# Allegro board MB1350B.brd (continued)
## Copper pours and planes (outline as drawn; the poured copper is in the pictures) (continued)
GND on TOP (solid shape): 73.03,140.5 72.52,141 72.01,140.49 72.01,141.86 73.03,141.86
GND on TOP: 72.14,125.35 69.98,127.51 69.98,138.18 73.41,138.18 73.41,139.06 72.39,139.06 72.39,140.84 69.98,140.84 69.98,148.72 72.39,151.13 92.08,151.13 95.25,147.96 95.25,126.49 94.11,125.35
GND on TOP: 58.55,54.86 61.98,54.86 62.36,54.48 65.91,54.48 66.17,54.23 66.17,52.45 65.79,52.07 62.74,52.07 61.59,53.21 58.8,53.21 58.55,52.96 58.55,51.69 58.29,51.44 55.37,51.44 55.12,51.69 55.12,53.72 55.37,53.98 57.66,53.98
GND on TOP: outline of 179 points within 0.51,0.51 113.79,172.21 ; 3 cut-outs
GND on TOP: 1.27,145.03 0.64,144.4 0.64,62.48 1.14,61.98 12.95,61.98 13.84,62.87 13.84,66.42 12.19,68.07 5.97,68.07 2.16,71.88 2.16,106.43 3.43,107.7 3.43,110.36 2.92,110.87 2.92,114.05 3.56,114.68 5.59,114.68 6.73,115.82 16.89,115.82 17.4,116.33 17.4,126.11 19.56,128.27 28.45,128.27 33.53,123.19 39.88,123.19 41.4,124.71 48.77,124.71 51.82,127.76 51.82,132.08 48.64,135.25 34.42,135.25 34.42,137.54 34.29,137.67 27.56,137.67 26.92,138.3 26.92,140.97 27.3,141.35 33.91,141.35 34.16,141.6 34.16,144.27 33.4,145.03 ; 1 cut-out
GND on TOP: 58.67,43.43 62.1,43.43 62.48,43.05 64.26,43.05 64.39,42.93 64.39,41.02 64.01,40.64 62.87,40.64 61.72,41.78 58.93,41.78 58.67,41.53 58.67,40.26 58.42,40.01 55.5,40.01 55.24,40.26 55.24,42.29 55.5,42.55 57.78,42.55
GND on TOP: 58.67,31.37 62.1,31.37 62.48,30.99 64.01,30.99 64.52,30.48 64.52,28.83 64.26,28.57 62.87,28.57 61.72,29.72 58.93,29.72 58.67,29.46 58.67,28.19 58.42,27.94 55.5,27.94 55.24,28.19 55.24,30.23 55.5,30.48 57.78,30.48
GND on TOP: 5.84,95.89 12.19,95.89 20.45,87.63 20.45,85.47 19.43,84.45 6.1,84.45 4.7,85.85 4.7,94.74
GND on BOTTOM: 26.04,82.17 42.67,82.17 44.32,80.52 44.32,66.29 49.28,61.34 49.28,57.53 47.75,56.01 29.46,56.01 26.92,58.55 26.92,65.66 25.53,67.06 25.53,81.66
GND on BOTTOM: outline of 126 points within 0.51,0.51 113.79,172.21 ; 2 cut-outs
GND on BOTTOM: 5.84,95.63 12.06,95.63 13.84,93.85 13.84,82.07 13.11,81.33 13.11,61.93 12.52,61.34 4.83,61.34 4.19,61.98 4.19,93.98
GND on BOTTOM: 62.74,80.77 80.26,80.77 80.77,80.26 89.92,80.26 90.17,80.01 90.17,72.9 86.11,68.83 86.11,62.61 84.84,61.34 66.93,61.34 54.61,73.66 48.9,73.66 47.88,74.68 47.88,79.38 49.28,80.77 53.21,80.77 53.21,79.25 53.85,78.61 56.26,78.61 57.4,79.76 61.72,79.76
GND on L3_GND: 0.51,0.51 0.51,172.21 113.79,172.21 113.79,109.65 113.51,108.97 113.26,107.19 112.93,104.8 113,102.74 113,101.3 113.44,98.76 113.79,97.38 113.79,0.51
VDD on L2_VCC: outline of 105 points within 27.43,0.51 113.79,154.43
VDD_ADJ on TOP: 66.42,55.37 66.04,54.99 62.48,54.99 62.23,55.24 61.21,55.24 60.96,55.5 60.96,63.12 59.82,64.26 53.85,64.26 53.47,64.64 53.47,66.67 54.1,67.31 65.79,67.31 66.42,66.67
VDD_ANA on TOP: 74.17,42.29 76.83,42.29 77.22,41.91 77.22,40.13 76.96,39.88 72.01,39.88 71.75,40.13 71.75,40.64 73.03,41.91 73.79,41.91
VDD_MCU on TOP (solid shape): 53.75,105.54 53.24,105.03 52.32,105.03 52.32,106.05 53.24,106.05
BOOTLOADER_RESET on TOP (solid shape): 45.73,54.76 45.22,54.25 44.3,54.25 44.3,55.27 45.22,55.27
E5V on TOP: 18.41,41.4 18.41,46.86 18.03,47.24 14.61,47.24 13.21,45.85 2.54,45.85 1.52,44.83 1.52,42.04 3.05,40.51 5.08,40.51 5.78,41.21 6.86,41.21 7.05,41.02 18.03,41.02
NETB2_2 on TOP (solid shape): 59.56,15.14 59.56,14.22 58.55,14.22 58.55,15.14 59.05,15.65
NETB3_1 on TOP (solid shape): 77.47,21.37 77.47,20.45 76.45,20.45 76.45,21.37 76.96,21.88
NETB3_2 on TOP (solid shape): 74.3,21.37 74.3,20.45 73.28,20.45 73.28,21.37 73.79,21.88
NETB3_3 on TOP (solid shape): 70.99,21.37 70.99,20.45 69.98,20.45 69.98,21.37 70.48,21.88
NETB3_4 on TOP (solid shape): 80.64,21.37 80.64,20.45 79.63,20.45 79.63,21.37 80.14,21.88
NETB3_6 on TOP (solid shape): 83.69,21.37 83.69,20.45 82.68,20.45 82.68,21.37 83.19,21.88
NETC11_2 on TOP (solid shape): 49.15,157.48 48.13,157.48 48.13,158.84 48.64,158.34 49.15,158.85
NETC26_2 on TOP: 42.93,119.51 48.26,119.51 48.64,119.13 48.64,117.22 48.01,116.59 44.83,116.59 44.45,116.2 44.45,112.9 44.07,112.52 42.8,112.52 42.55,112.78 42.55,119.13
NETC63_1 on TOP (solid shape): 51.71,50.95 50.79,50.95 50.29,51.46 50.79,51.97 51.71,51.97
NETC63_2 on TOP (solid shape): 48.54,50.95 47.62,50.95 47.11,51.46 47.62,51.97 48.54,51.97
NETC63_2 on TOP (solid shape): 50.03,51.46 50.54,50.95 49.17,50.95 49.17,51.97 50.54,51.97
NETC79_1 on TOP: 14.99,29.59 19.05,29.59 19.56,30.1 19.56,37.97 18.92,38.61 15.37,38.61 14.86,38.1 14.86,33.53 14.73,33.4 14.73,29.84
NETC79_2 on TOP: 9.91,19.68 3.17,19.68 2.16,20.7 2.16,31.5 9.27,38.61 13.46,38.61 14.22,37.85 14.22,30.23 14.1,30.1 8.26,30.1 7.87,29.72 7.87,24.77 10.41,22.23 10.41,20.19
NETC90_2 on TOP (solid shape): 91.44,15.02 91.44,14.1 90.42,14.1 90.42,15.02 90.93,15.53
NETCN8_10 on TOP (solid shape): 110.24,112.9 109.32,112.9 108.81,113.41 109.32,113.92 110.24,113.92
NETCN9_18 on TOP (solid shape): 53.47,80.39 52.45,80.39 52.45,81.75 52.96,81.25 53.47,81.76
NETCN9_19 on TOP (solid shape): 49.66,81.31 49.66,80.39 48.64,80.39 48.64,81.31 49.15,81.82
NETCN10_13 on TOP (solid shape): 62.1,82.01 61.59,81.5 61.09,82.01 61.09,82.93 62.1,82.93
NETCN10_15 on TOP (solid shape): 58.04,82.01 57.53,81.5 57.02,82.01 57.02,82.93 58.04,82.93
NETCN10_20 on BOTTOM (solid shape): 84.2,82.42 82.84,82.42 83.35,82.93 82.84,83.44 84.2,83.44
NETCN10_22 on BOTTOM (solid shape): 84.2,80.9 82.84,80.9 83.35,81.41 82.84,81.92 84.2,81.92
NETCN11_9 on TOP (solid shape): 48.54,47.14 47.62,47.14 47.11,47.65 47.62,48.16 48.54,48.16
NETCN11_9 on TOP (solid shape): 50.6,47.65 50.1,47.14 49.17,47.14 49.17,48.16 50.1,48.16
NETCN14_1 on TOP (solid shape): 94.23,59.44 93.31,59.44 92.81,59.94 93.31,60.45 94.23,60.45
NETCN16_1 on TOP: 14.35,29.21 16.26,29.21 16.76,28.7 16.76,25.65 14.99,23.88 9.91,23.88 8.64,25.15 8.64,29.21 9.02,29.59 13.97,29.59
NETR13_1 on TOP (solid shape): 53.69,141.35 54.2,140.84 52.83,140.84 52.83,141.86 54.19,141.86
NETR34_1 on TOP (solid shape): 97.41,107.95 96.49,107.95 95.98,108.46 96.49,108.97 97.41,108.97
NETR40_1 on TOP (solid shape): 38.51,84.71 38,84.2 37.08,84.2 37.08,85.22 38,85.22
NETR56_1 on TOP (solid shape): 88.8,65.28 88.3,64.77 87.38,64.77 87.38,65.79 88.3,65.79
NETR57_1 on TOP (solid shape): 91.69,66.39 91.19,65.88 90.68,66.39 90.68,67.31 91.69,67.31
NETR76_1 on TOP (solid shape): 97.41,106.43 96.49,106.43 95.98,106.93 96.49,107.44 97.41,107.44
NETR77_1 on TOP (solid shape): 46.85,51.46 47.36,50.95 46,50.95 46,51.97 47.36,51.97
NETR82_2 on TOP (solid shape): 51.71,47.14 50.35,47.14 50.86,47.65 50.35,48.16 51.71,48.16
NETR85_1 on TOP (solid shape): 46.85,47.65 47.36,47.14 46,47.14 46,48.16 47.36,48.16
NETR101_1 on TOP (solid shape): 25.27,24 24.26,24 24.26,25.36 24.76,24.86 25.27,25.37
NETR102_1 on TOP (solid shape): 26.92,24 25.91,24 25.91,25.36 26.41,24.86 26.92,25.37
NETR103_1 on TOP (solid shape): 28.57,24 27.56,24 27.56,25.36 28.06,24.86 28.57,25.37
NETR104_1 on TOP (solid shape): 30.23,24 29.21,24 29.21,25.36 29.72,24.86 30.23,25.37
NETSB4_1 on TOP (solid shape): 53.69,143 54.2,142.49 52.83,142.49 52.83,143.51 54.19,143.51
NETSB10_1 on TOP (solid shape): 54.86,106.93 53.5,106.93 54.01,107.44 53.5,107.95 54.86,107.95
NETSB10_1 on TOP (solid shape): 54.86,105.03 53.5,105.03 54.01,105.53 53.5,106.05 54.86,106.05
NETSB11_1 on TOP (solid shape): 56.35,107.44 56.86,106.93 55.5,106.93 55.5,107.95 56.86,107.95
NETSB11_1 on TOP (solid shape): 56.35,105.54 56.86,105.03 55.5,105.03 55.5,106.05 56.86,106.05
NETSB15_1 on TOP (solid shape): 96.01,99.86 95.51,100.36 95,99.85 95,101.22 96.01,101.22
NETSB24_2 on TOP (solid shape): 81.66,66.67 80.74,66.67 80.23,67.18 80.74,67.69 81.66,67.69
PA0 on TOP (solid shape): 74.3,21.63 73.79,22.13 73.28,21.62 73.28,22.99 74.3,22.99
PA7 on TOP (solid shape): 79.98,67.19 80.49,66.67 79.12,66.67 79.12,67.69 80.48,67.69
PA11 on TOP (solid shape): 46.84,54.25 45.48,54.25 45.98,54.76 45.47,55.27 46.84,55.27
PA12 on TOP (solid shape): 39.62,84.2 38.26,84.2 38.77,84.71 38.26,85.22 39.62,85.22
PA13 on TOP (solid shape): 55.37,142.49 54.45,142.49 53.94,143 54.45,143.51 55.37,143.51
PB2 on TOP (solid shape): 56.52,80.39 55.15,80.39 55.66,80.9 55.15,81.41 56.52,81.41
PB2 on TOP (solid shape): 91.44,15.28 90.93,15.78 90.42,15.27 90.42,16.64 91.44,16.64
PB3 on TOP (solid shape): 91.69,64.77 90.68,64.77 90.68,66.13 91.18,65.63 91.69,66.14
PB4 on TOP (solid shape): 95.72,106.94 96.23,106.43 94.87,106.43 94.87,107.44 96.23,107.44
PB8 on TOP (solid shape): 92.55,59.95 93.06,59.44 91.69,59.44 91.69,60.45 93.06,60.45
PC1 on TOP (solid shape): 51.18,157.48 50.16,157.48 50.16,158.84 50.67,158.34 51.18,158.85
PC2 on TOP (solid shape): 83.69,21.63 83.19,22.13 82.68,21.62 82.68,22.99 83.69,22.99
PC3 on TOP (solid shape): 70.99,21.63 70.49,22.13 69.98,21.62 69.98,22.99 70.99,22.99
PC6 on TOP (solid shape): 49.15,159.1 48.64,158.59 48.13,159.1 48.13,160.02 49.15,160.02
PC7 on TOP (solid shape): 80.64,21.63 80.14,22.13 79.63,21.62 79.63,22.99 80.64,22.99
PC8 on TOP (solid shape): 77.47,21.63 76.96,22.13 76.45,21.62 76.45,22.99 77.47,22.99
PC9 on TOP (solid shape): 108.55,113.41 109.06,112.9 107.7,112.9 107.7,113.92 109.06,113.92
PC10 on TOP (solid shape): 55.37,140.84 54.45,140.84 53.94,141.35 54.45,141.86 55.37,141.86
PC12 on TOP (solid shape): 89.92,64.77 88.55,64.77 89.06,65.28 88.55,65.79 89.92,65.79
PC13 on TOP (solid shape): 59.56,15.4 59.06,15.91 58.55,15.4 58.55,16.76 59.56,16.76
PC14 on TOP (solid shape): 49.66,81.57 49.15,82.08 48.64,81.57 48.64,82.93 49.66,82.93
PC15 on TOP (solid shape): 53.47,82.01 52.96,81.5 52.45,82.01 52.45,82.93 53.47,82.93
PD0 on TOP (solid shape): 51.18,159.1 50.67,158.59 50.16,159.1 50.16,160.02 51.18,160.02
PD1 on TOP (solid shape): 95.72,108.46 96.23,107.95 94.87,107.95 94.87,108.97 96.23,108.97
PD5 on TOP (solid shape): 30.23,25.62 29.72,25.11 29.21,25.62 29.21,26.54 30.23,26.54
PD6 on TOP (solid shape): 28.57,25.62 28.07,25.11 27.56,25.62 27.56,26.54 28.57,26.54
PD8 on TOP (solid shape): 26.92,25.62 26.42,25.11 25.91,25.62 25.91,26.54 26.92,26.54
PD8 on TOP (solid shape): 58.04,106.93 57.12,106.93 56.61,107.44 57.12,107.95 58.04,107.95
PD9 on TOP (solid shape): 25.27,25.62 24.77,25.11 24.26,25.62 24.26,26.54 25.27,26.54
PD9 on TOP (solid shape): 53.75,107.44 53.24,106.93 52.32,106.93 52.32,107.95 53.24,107.95
PF0 on TOP (solid shape): 58.04,80.39 57.02,80.39 57.02,81.75 57.53,81.25 58.04,81.76
PF1 on TOP (solid shape): 62.1,80.39 61.09,80.39 61.09,81.75 61.59,81.25 62.1,81.76
PF2 on TOP (solid shape): 64.01,80.36 63.5,79.85 62.99,80.36 62.99,81.28 64.01,81.28
PF3 on BOTTOM (solid shape): 83.09,82.93 82.58,82.42 81.66,82.42 81.66,83.44 82.58,83.44
PF4 on TOP (solid shape): 55.4,82.55 54.9,82.04 53.98,82.04 53.98,83.06 54.9,83.06
PF4 on TOP (solid shape): 55.4,80.9 54.9,80.39 53.98,80.39 53.98,81.41 54.9,81.41
PF4 on BOTTOM (solid shape): 83.09,81.41 82.58,80.9 81.66,80.9 81.66,81.92 82.58,81.92
RESET# on TOP (solid shape): 64.01,78.74 62.99,78.74 62.99,80.1 63.5,79.6 64.01,80.11
STLINK_RX on TOP (solid shape): 65.94,143.51 65.44,143 64.52,143 64.52,144.02 65.44,144.02
STLK_RX on TOP (solid shape): 67.06,143 65.69,143 66.2,143.51 65.69,144.02 67.06,144.02
STM_RST on TOP (solid shape): 73.03,140.24 73.03,139.32 72.01,139.32 72.01,140.24 72.52,140.75
U5V_ST_LINK on TOP (solid shape): 25.15,124.21 24.23,124.21 23.72,124.71 24.23,125.22 25.15,125.22
U5V_ST_LINK on TOP: 24.13,124.84 24.77,125.48 25.91,125.48 26.16,125.22 26.16,122.05 25.78,121.67 24.64,121.67 24.13,122.17
VREF+ on TOP (solid shape): 56.52,82.04 55.15,82.04 55.66,82.55 55.15,83.06 56.52,83.06
VUSB_ST_LINK on TOP (solid shape): 23.46,124.72 23.97,124.21 22.61,124.21 22.61,125.22 23.97,125.22
VUSB_ST_LINK on TOP: 19.05,110.62 17.91,111.76 17.91,125.6 18.54,126.24 23.24,126.24 23.62,125.86 23.62,124.59 23.24,124.21 20.7,124.21 20.07,123.57 20.07,116.08 21.72,114.43 23.5,114.43 24.26,115.19 24.26,118.87 24.51,119.13 25.65,119.13 26.16,118.62 28.7,118.62 29.46,117.86 29.46,111.63 28.45,110.62
VUSB_ST_LINK on BOTTOM: 7.11,140.08 8.26,140.08 8.51,139.83 8.51,139.32 13.08,134.75 14.35,134.75 15.88,133.22 15.88,128.91 19.43,125.35 19.43,124.97 18.41,123.95 17.65,123.95 14.22,127.38 14.22,132.59 13.72,133.1 12.45,133.1 6.86,138.68 6.86,139.83

Small or netless copper shapes (teardrops, artwork), in the pictures only: 2 on TOP

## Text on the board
Ref Des/Silkscreen Bottom: STLINK | B
Ref Des/Silkscreen Top: ST-LINK/V2-1 | Power source | USART1 | PWR_EXT | STLK_TX | EXT I2C | VDD<2.7V | PSU DC5V | 5V | PD8 | PC7 | PA12 | PC9 | PD5 | PD6 | PC4 | PC10 | GND | PC14 | PC13 | RS232_RX | RS485_RX | MC | PD9 | PA11 | PC8 | PD1 | PC5 | PB4 | PC11 | PC15 | D5V | +3V3 | TX | RX | VDD_ANA | 2002/95/EC | 12C_PU | RESET# | COMPLIANT | PA15 | PC6 | PA1 | PB6 | PB7 | PB13 | PB14 | PB1 | PB10 | PA3 | PB12 | PB11 | VDD | RX_BOOT | TX_BOOT | BL_RST | BAT | Vref+ | VDD_ADJ | Motor control | 3V3 | SWCLK | Audio_L | VDD_MCU | Audio_IN | BOOT0 | Audio_R | PA14/BOOT0 | PA7 | PA5 | PA13 | PB8 | PA0 | PC2 | PF1 | PF0 | Audio Shutdown | SWD | PB2 | PA6 | PA4 | PB3 | PC0 | PC3 | PC12 | PF2 | PF3 | PF4 | +5V | PA8 | PB15 | PA9 | PA10 | PD4 | PB9 | PA2 | PB0 | PB5 | PC1 | PD0 | PD2 | PD3 | EXT_IC2_PWR | +3V3_SD | LCD | uSD | AIN | Audio | U5V | PSU | COM | STlk | STLINK | MIC+ | MIC_OUT | A | VBAT | B | S | Reset | Tamper | Joystick | MB1350B | ADC_channel | STM32G081B-EVAL
User.31: U1
User.36: FIGURE | SIZE | 12.0 | 30.0 | 33.0 | 36.0 | 38.0 | 40.0 | 48.0 | 28.0 | 39.0 | 47.0 | 58.0 | 79.0 | 126.0 | 138.0 | 51.0x24.0 | 126.0x40.0 | 140.0x50.0 | DRILL CHART: TOP to BOTTOM | ALL UNITS ARE IN MILS | TOLERANCE | +3.0/-3.0 | +2.0/-2.0 | +5.0/-5.0 | PLATED | NON-PLATED | QTY | 522 | 6 | 2 | 88 | 9 | 135 | 3 | 1 | 5
